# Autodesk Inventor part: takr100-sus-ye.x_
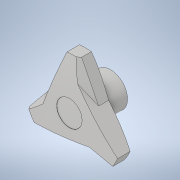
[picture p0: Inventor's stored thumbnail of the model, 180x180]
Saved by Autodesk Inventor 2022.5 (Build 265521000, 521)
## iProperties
Created: 2021-08
Part Number: takr100-sus-ye.x_
Material: 一般
Document SubType Name: Modeling
Designer: ImaoCorp
Density: 1 g/cm^3
Appearance: 既定
Sending System: SOLIDWORKS 2019-2019304
MC: AMD64
MC_MODEL: Intel64 Family 6 Model 60 Stepping 3, GenuineIntel
OS: Windows_NT
FRU: Parasolid Version 31.0, build 290,  9- 1-2019
FORMAT: text
GUISE: transmit
KEY: takr100-sus-ye
FILE: takr100-sus-ye.x_t
DATE: Wed Aug 11 15:02:03 2021
Author: ImaoCorp
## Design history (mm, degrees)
feature "Base1"
node "ソリッド1"
